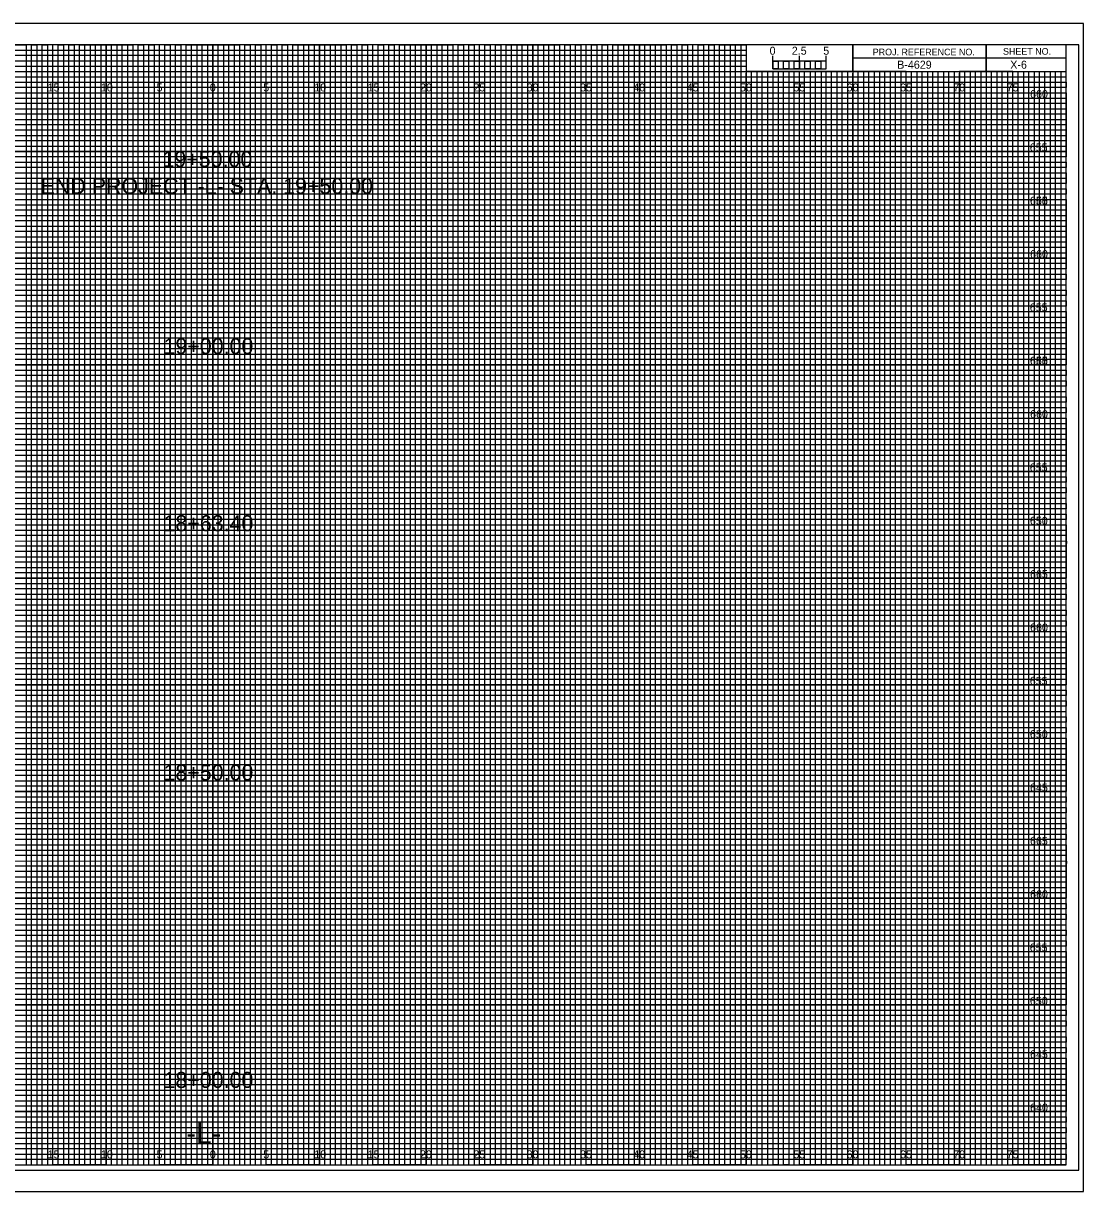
# Model space of a CAD drawing. Extents: x -7 to 162, y 548 to 657.
# Drawn here: x 62.2 to 161.7, y 547.5 to 657 of the extents above; entities that cross this region are included whole.
import ezdxf

# ---------------------------------------------------------------- set-up
doc = ezdxf.new("R2010")
doc.units = 0
for name, color, linetype in [('Exist CMT Pavement', 7, 'Continuous'), ('Exist Cross Section Cell', 7, 'Continuous'), ('Exist XS Center Line Elevation Label', 7, 'Continuous'), ('Exist XS Ground Line', 7, 'Continuous'), ('Prop CMT Pvmt Course 1 Wedge', 7, 'Continuous'), ('Prop CMT Pvmt Course 2 Wedge', 7, 'Continuous'), ('Prop CMT Pvmt Course 3 Wedge', 7, 'Continuous'), ('Prop CMT Pvmt Surface', 7, 'Continuous'), ('Prop CMT Pvmt Surface Shoulder', 7, 'Continuous'), ('Prop CMT Pvmt Wedge Surface 1', 7, 'Continuous'), ('Prop CMT Pvmt Wedge Surface 2', 7, 'Continuous'), ('Prop CMT Shld Paved Course 1', 7, 'Continuous'), ('Prop CMT Shld Paved Course 2', 7, 'Continuous'), ('Prop CMT Shld Paved Course 3', 7, 'Continuous'), ('Prop CMT Slope Grass', 7, 'Continuous'), ('Prop CMT Subgrade Earthwork', 7, 'Continuous'), ('Prop XS EOT Tick Mark', 7, 'Continuous')]:
    doc.layers.add(name, color=color, linetype=linetype)

msp = doc.modelspace()

# ---------------------------------------------------------------- linework, layer by layer
at = {"layer": 'Exist XS Center Line Elevation Label'}
for points in [[(57.5, 655), (62.5, 655), (62.5, 550), (67.5, 550), (67.5, 655), (72.5, 655), (72.5, 550), (77.5, 550), (77.5, 655), (82.5, 655), (82.5, 550), (87.5, 550), (87.5, 655), (92.5, 655), (92.5, 550), (97.5, 550), (97.5, 655), (102.5, 655), (102.5, 550), (107.5, 550), (107.5, 655), (112.5, 655), (112.5, 550), (117.5, 550), (117.5, 655), (122.5, 655), (122.5, 550), (127.5, 550), (127.5, 655), (129.97, 655), (130, 655), (130, 652.5), (132.5, 652.5), (132.5, 550), (137.5, 550), (137.5, 652.5), (142.5, 652.5), (142.5, 550), (147.5, 550), (147.5, 652.5), (152.5, 652.5), (152.5, 550), (157.5, 550), (157.5, 652.5)], [(0, 652.5), (137.5, 652.5)], [(0, 642.5), (160, 642.5), (160, 647.5), (0, 647.5)], [(0, 632.5), (160, 632.5), (160, 637.5), (0, 637.5)], [(0, 622.5), (160, 622.5), (160, 627.5), (0, 627.5)], [(0, 612.5), (160, 612.5), (160, 617.5), (0, 617.5)], [(0, 602.5), (160, 602.5), (160, 607.5), (0, 607.5)], [(0, 592.5), (160, 592.5), (160, 597.5), (0, 597.5)], [(0, 582.5), (160, 582.5), (160, 587.5), (0, 587.5)], [(0, 572.5), (160, 572.5), (160, 577.5), (0, 577.5)], [(0, 562.5), (160, 562.5), (160, 567.5), (0, 567.5)], [(0, 552.5), (160, 552.5), (160, 557.5), (0, 557.5)]]:
    msp.add_lwpolyline(points, dxfattribs=at)
at = {"layer": 'Exist XS Ground Line'}
for p, q in [((65, 655), (60, 655)), ((65, 550), (65, 655)), ((75, 655), (70, 655)), ((70, 655), (70, 550)), ((75, 550), (75, 655)), ((85, 655), (80, 655)), ((80, 655), (80, 550)), ((85, 550), (85, 655)), ((95, 655), (90, 655)), ((90, 655), (90, 550)), ((95, 550), (95, 655)), ((105, 655), (100, 655)), ((100, 655), (100, 550)), ((105, 550), (105, 655)), ((115, 655), (110, 655)), ((110, 655), (110, 550)), ((115, 550), (115, 655)), ((125, 655), (120, 655)), ((120, 655), (120, 550)), ((125, 550), (125, 655)), ((130, 655), (130, 550)), ((135, 550), (135, 652.5)), ((145, 652.5), (140, 652.5)), ((140, 652.5), (140, 550)), ((145, 550), (145, 652.5)), ((155, 652.5), (150, 652.5)), ((150, 652.5), (150, 550)), ((155, 550), (155, 652.5)), ((70, 550), (65, 550)), ((80, 550), (75, 550)), ((90, 550), (85, 550)), ((100, 550), (95, 550)), ((110, 550), (105, 550)), ((120, 550), (115, 550)), ((130, 550), (125, 550)), ((140, 550), (135, 550)), ((150, 550), (145, 550)), ((160, 550), (155, 550)), ((160, 550), (160, 550))]:
    msp.add_line(p, q, dxfattribs=at)
for points in [[(0, 650), (160, 650), (160, 645), (0, 645)], [(0, 640), (160, 640), (160, 635), (0, 635)], [(0, 630), (160, 630), (160, 625), (0, 625)], [(0, 620), (160, 620), (160, 615), (0, 615)], [(0, 610), (160, 610), (160, 605), (0, 605)], [(0, 600), (160, 600), (160, 595), (0, 595)], [(0, 590), (160, 590), (160, 585), (0, 585)], [(0, 580), (160, 580), (160, 575), (0, 575)], [(0, 570), (160, 570), (160, 565), (0, 565)], [(0, 560), (160, 560), (160, 555), (0, 555)]]:
    msp.add_lwpolyline(points, dxfattribs=at)
at = {"layer": 'Prop CMT Pvmt Course 1 Wedge'}
for p, q in [((161.65, 657), (-6.7, 657)), ((-6.7, 547.5), (161.65, 547.5))]:
    msp.add_line(p, q, dxfattribs=at)
at = {"layer": 'Prop CMT Pvmt Surface'}
for p, q in [((133.5, 652.5), (133, 652.5)), ((133, 652.5), (133, 550)), ((133.5, 550), (133.5, 652.5)), ((134.5, 652.5), (134, 652.5)), ((134, 652.5), (134, 550)), ((134.5, 550), (134.5, 652.5)), ((133, 550), (132.5, 550)), ((134, 550), (133.5, 550))]:
    msp.add_line(p, q, dxfattribs=at)
for points in [[(62.5, 550), (63, 550), (63, 655), (63.5, 655), (63.5, 550)], [(63.5, 550), (64, 550), (64, 655), (64.5, 655), (64.5, 550)], [(65, 550), (65.5, 550), (65.5, 655), (66, 655), (66, 550)], [(66, 550), (66.5, 550), (66.5, 655), (67, 655), (67, 550)], [(67.5, 550), (68, 550), (68, 655), (68.5, 655), (68.5, 550)], [(68.5, 550), (69, 550), (69, 655), (69.5, 655), (69.5, 550)], [(70, 550), (70.5, 550), (70.5, 655), (71, 655), (71, 550)], [(71, 550), (71.5, 550), (71.5, 655), (72, 655), (72, 550)], [(72.5, 550), (73, 550), (73, 655), (73.5, 655), (73.5, 550)], [(73.5, 550), (74, 550), (74, 655), (74.5, 655), (74.5, 550)], [(75, 550), (75.5, 550), (75.5, 655), (76, 655), (76, 550)], [(76, 550), (76.5, 550), (76.5, 655), (77, 655), (77, 550)], [(77.5, 550), (78, 550), (78, 655), (78.5, 655), (78.5, 550)], [(78.5, 550), (79, 550), (79, 655), (79.5, 655), (79.5, 550)], [(80, 550), (80.5, 550), (80.5, 655), (81, 655), (81, 550)], [(81, 550), (81.5, 550), (81.5, 655), (82, 655), (82, 550)], [(82.5, 550), (83, 550), (83, 655), (83.5, 655), (83.5, 550)], [(83.5, 550), (84, 550), (84, 655), (84.5, 655), (84.5, 550)], [(85, 550), (85.5, 550), (85.5, 655), (86, 655), (86, 550)], [(86, 550), (86.5, 550), (86.5, 655), (87, 655), (87, 550)], [(87.5, 550), (88, 550), (88, 655), (88.5, 655), (88.5, 550)], [(88.5, 550), (89, 550), (89, 655), (89.5, 655), (89.5, 550)], [(90, 550), (90.5, 550), (90.5, 655), (91, 655), (91, 550)], [(91, 550), (91.5, 550), (91.5, 655), (92, 655), (92, 550)], [(92.5, 550), (93, 550), (93, 655), (93.5, 655), (93.5, 550)], [(93.5, 550), (94, 550), (94, 655), (94.5, 655), (94.5, 550)], [(95, 550), (95.5, 550), (95.5, 655), (96, 655), (96, 550)], [(96, 550), (96.5, 550), (96.5, 655), (97, 655), (97, 550)], [(97.5, 550), (98, 550), (98, 655), (98.5, 655), (98.5, 550)], [(98.5, 550), (99, 550), (99, 655), (99.5, 655), (99.5, 550)], [(100, 550), (100.5, 550), (100.5, 655), (101, 655), (101, 550)], [(101, 550), (101.5, 550), (101.5, 655), (102, 655), (102, 550)], [(102.5, 550), (103, 550), (103, 655), (103.5, 655), (103.5, 550)], [(103.5, 550), (104, 550), (104, 655), (104.5, 655), (104.5, 550)], [(105, 550), (105.5, 550), (105.5, 655), (106, 655), (106, 550)], [(106, 550), (106.5, 550), (106.5, 655), (107, 655), (107, 550)], [(107.5, 550), (108, 550), (108, 655), (108.5, 655), (108.5, 550)], [(108.5, 550), (109, 550), (109, 655), (109.5, 655), (109.5, 550)], [(110, 550), (110.5, 550), (110.5, 655), (111, 655), (111, 550)], [(111, 550), (111.5, 550), (111.5, 655), (112, 655), (112, 550)], [(112.5, 550), (113, 550), (113, 655), (113.5, 655), (113.5, 550)], [(113.5, 550), (114, 550), (114, 655), (114.5, 655), (114.5, 550)], [(115, 550), (115.5, 550), (115.5, 655), (116, 655), (116, 550)], [(116, 550), (116.5, 550), (116.5, 655), (117, 655), (117, 550)], [(117.5, 550), (118, 550), (118, 655), (118.5, 655), (118.5, 550)], [(118.5, 550), (119, 550), (119, 655), (119.5, 655), (119.5, 550)], [(120, 550), (120.5, 550), (120.5, 655), (121, 655), (121, 550)], [(121, 550), (121.5, 550), (121.5, 655), (122, 655), (122, 550)], [(122.5, 550), (123, 550), (123, 655), (123.5, 655), (123.5, 550)], [(123.5, 550), (124, 550), (124, 655), (124.5, 655), (124.5, 550)], [(125, 550), (125.5, 550), (125.5, 655), (126, 655), (126, 550)], [(126, 550), (126.5, 550), (126.5, 655), (127, 655), (127, 550)], [(127.5, 550), (128, 550), (128, 655), (128.5, 655), (128.5, 550)], [(128.5, 550), (129, 550), (129, 655), (129.5, 655), (129.5, 550)], [(130, 550), (130.5, 550), (130.5, 652.5), (131.01, 652.5), (131.01, 550)], [(131, 550), (131.5, 550), (131.5, 652.5), (132, 652.5), (132, 550)], [(135, 550), (135.49, 550), (135.49, 652.5), (136, 652.5), (136, 550)], [(136, 550), (136.5, 550), (136.5, 652.5), (137.03, 652.5), (137.03, 550)], [(137.5, 550), (138, 550), (138, 652.5), (138.5, 652.5), (138.5, 550)], [(138.5, 550), (139, 550), (139, 652.5), (139.5, 652.5), (139.5, 550)], [(140, 550), (140.5, 550), (140.5, 652.5), (141, 652.5), (141, 550)], [(141, 550), (141.5, 550), (141.5, 652.5), (142, 652.5), (142, 550)], [(142.5, 550), (143, 550), (143, 652.5), (143.5, 652.5), (143.5, 550)], [(143.5, 550), (144, 550), (144, 652.5), (144.5, 652.5), (144.5, 550)], [(145, 550), (145.5, 550), (145.5, 652.5), (146, 652.5), (146, 550)], [(146, 550), (146.5, 550), (146.5, 652.5), (147, 652.5), (147, 550)], [(147.5, 550), (148, 550), (148, 652.5), (148.5, 652.5), (148.5, 550)], [(148.5, 550), (149, 550), (149, 652.5), (149.5, 652.5), (149.5, 550)], [(150, 550), (150.5, 550), (150.5, 652.5), (151, 652.5), (151, 550)], [(151, 550), (151.5, 550), (151.5, 652.5), (152, 652.5), (152, 550)], [(152.5, 550), (153, 550), (153, 652.5), (153.5, 652.5), (153.5, 550)], [(153.5, 550), (154, 550), (154, 652.5), (154.5, 652.5), (154.5, 550)], [(155, 550), (155.5, 550), (155.5, 652.5), (156, 652.5), (156, 550)], [(156, 550), (156.5, 550), (156.5, 652.5), (157, 652.5), (157, 550)], [(157.5, 550), (158, 550), (158, 652.5), (158.5, 652.5), (158.5, 550)], [(158.5, 550), (159, 550), (159, 652.5), (159.5, 652.5), (159.5, 550)]]:
    msp.add_lwpolyline(points, dxfattribs=at)
at = {"layer": 'Prop CMT Pvmt Surface Shoulder'}
for p, q in [((132.5, 652.75), (132.5, 653.95)), ((132.5, 653.45), (132.5, 653.95)), ((135, 652.75), (135, 653.95)), ((137.5, 652.75), (137.5, 653.95)), ((137.5, 653.45), (137.5, 653.95))]:
    msp.add_line(p, q, dxfattribs=at)
for points in [[(137.5, 653.45), (132.5, 653.45), (132.5, 652.75), (137.5, 652.75)], [(132.5, 653.45), (133, 653.45), (133, 652.75), (132.5, 652.75)], [(133.5, 653.45), (134, 653.45), (134, 652.75), (133.5, 652.75)], [(134.5, 653.45), (135, 653.45), (135, 652.75), (134.5, 652.75)], [(135.5, 653.45), (136, 653.45), (136, 652.75), (135.5, 652.75)], [(136.5, 653.45), (137, 653.45), (137, 652.75), (136.5, 652.75)]]:
    msp.add_lwpolyline(points, close=True, dxfattribs=at)
at = {"layer": 'Prop CMT Shld Paved Course 1'}
msp.add_lwpolyline([(-6.7, 547.5), (161.65, 547.5), (161.65, 657), (-6.7, 657)], close=True, dxfattribs=at)
at = {"layer": 'Prop CMT Shld Paved Course 2'}
msp.add_lwpolyline([(-5.4, 549.5), (161.2, 549.5), (161.2, 655), (-5.4, 655)], close=True, dxfattribs=at)
at = {"layer": 'Prop CMT Shld Paved Course 3'}
for p, q in [((65, 550), (65, 655)), ((70, 550), (70, 655)), ((75, 550), (75, 655)), ((80, 550), (80, 655)), ((85, 550), (85, 655)), ((90, 550), (90, 655)), ((95, 550), (95, 655)), ((100, 550), (100, 655)), ((105, 550), (105, 655)), ((110, 550), (110, 655)), ((115, 550), (115, 655)), ((120, 550), (120, 655)), ((125, 550), (125, 655)), ((130, 550), (130, 652.34)), ((135, 550), (135, 652.34)), ((140, 550), (140, 652.34)), ((145, 550), (145, 652.34)), ((150, 550), (150, 652.34)), ((155, 550), (155, 652.34)), ((0, 650), (160, 650)), ((0, 645), (160, 645)), ((0, 640), (160, 640)), ((0, 635), (160, 635)), ((0, 630), (160, 630)), ((0, 625), (160, 625)), ((0, 620), (160, 620)), ((0, 615), (160, 615)), ((0, 610), (160, 610)), ((0, 605), (160, 605)), ((0, 600), (160, 600)), ((0, 595), (160, 595)), ((0, 590), (160, 590)), ((0, 585), (160, 585)), ((0, 580), (160, 580)), ((0, 575), (160, 575)), ((0, 570), (160, 570)), ((0, 565), (160, 565)), ((0, 560), (160, 560)), ((0, 555), (160, 555))]:
    msp.add_line(p, q, dxfattribs=at)
at = {"layer": 'Prop CMT Slope Grass'}
for p, q in [((152.5, 655), (152.5, 652.5)), ((152.5, 652.5), (152.5, 655)), ((160, 653.75), (140, 653.75)), ((140, 653.75), (140, 652.5)), ((140, 652.5), (160, 652.5))]:
    msp.add_line(p, q, dxfattribs=at)
for points in [[(160, 655), (0, 655), (0, 550), (160, 550)], [(140, 655), (130, 655), (130, 652.51), (140, 652.51)], [(160, 655), (140, 655), (140, 652.5), (160, 652.5)]]:
    msp.add_lwpolyline(points, close=True, dxfattribs=at)
at = {"layer": 'Prop XS EOT Tick Mark'}
for p, q in [((0, 654.5), (130, 654.5)), ((130, 653.99), (0, 653.99)), ((130, 654.5), (130, 653.99)), ((0, 653.5), (130, 653.5)), ((130, 652.95), (0, 652.95)), ((130, 653.5), (130, 652.95)), ((0, 652), (160, 652))]:
    msp.add_line(p, q, dxfattribs=at)
for points in [[(0, 651.5), (135, 651.5), (160, 651.5), (160, 651), (0, 651)], [(0, 650.5), (160, 650.5), (160, 649.5), (0, 649.5)], [(0, 649), (160, 649), (160, 648.5), (0, 648.49)], [(0, 648), (160, 648), (160, 647), (0, 647)], [(0, 646.5), (160, 646.5), (160, 646), (0, 646)], [(0, 645.5), (160, 645.5), (160, 644.5), (0, 644.5)], [(0, 644), (160, 644), (160, 643.5), (0, 643.5)], [(0, 643), (160, 643), (160, 642), (0, 642)], [(0, 641.5), (160, 641.5), (160, 641), (0, 641)], [(0, 640.5), (160, 640.5), (160, 639.5), (0, 639.5)], [(0, 639), (160, 639), (160, 638.5), (0, 638.5)], [(0, 638), (160, 638), (160, 636.98), (160, 636.5), (160, 636), (0, 636)], [(0, 637), (160, 637), (160, 636.5), (0, 636.5)], [(0, 635.5), (160, 635.5), (160, 634.5), (0, 634.51)], [(0, 634.51), (160, 634.5), (160, 634), (0, 634)], [(0, 633.5), (160, 633.5), (160, 633), (0, 633)], [(0, 632), (160, 632), (160, 631.5), (0, 631.5)], [(0, 631), (160, 631), (160, 630.5), (0, 630.5)], [(-0.04, 629.45), (160, 629.45), (160, 628.94), (-0.04, 628.94)], [(0, 628.5), (160, 628.5), (160, 628), (0, 628)], [(0, 627), (160, 627), (160, 626.5), (0, 626.5)], [(0, 626), (160, 626), (160, 625.5), (0, 625.5)], [(0, 624.5), (160, 624.5), (160, 624), (0, 624)], [(0, 623.5), (160, 623.5), (160, 623), (0, 623)], [(0, 622), (160, 622), (160, 621.5), (0, 621.5)], [(0, 621), (160, 621), (160, 620.5), (0, 620.5)], [(0, 619.5), (160, 619.5), (160, 618.99), (0, 619)], [(0, 618.5), (160, 618.5), (160, 618), (0, 618)], [(0, 617), (160, 617), (160, 616.5), (0, 616.5)], [(0, 616), (160, 616), (160, 615.5), (0, 615.5)], [(0, 614.5), (160, 614.5), (160, 614), (0, 614)], [(0, 613.5), (160, 613.5), (160, 613), (0, 613)], [(0, 612), (160, 612), (160, 611.5), (0, 611.5)], [(0, 611), (160, 611), (160, 610.5), (0, 610.5)], [(0, 609.5), (160, 609.5), (160, 609), (0, 609)], [(0, 608.5), (160.03, 608.46), (160, 608), (0, 608)], [(0, 607), (160, 607), (160, 606.5), (0, 606.5)], [(0, 606), (160, 606), (160, 605.5), (0, 605.5)], [(0, 604.5), (160, 604.5), (160, 604), (0, 604)], [(0, 603.5), (160, 603.5), (160, 603), (0, 603)], [(0, 602), (160, 602), (160, 601.5), (0, 601.5)], [(0, 601), (160, 601), (160, 600.5), (0, 600.5)], [(0, 599.5), (160, 599.5), (160, 599), (0, 599)], [(0, 598.5), (160, 598.5), (160, 598), (0, 598)], [(0, 597), (160, 597), (160, 596.5), (0, 596.5)], [(0, 596), (160, 596), (160, 595.5), (0, 595.5)], [(0, 594.5), (160, 594.5), (160, 594), (0, 594)], [(0, 593.5), (160, 593.5), (160, 593), (0, 593)], [(0, 592), (160, 592), (160, 591.5), (0, 591.5)], [(0, 591), (160, 591), (160, 590.5), (0, 590.5)], [(0, 589.5), (160, 589.5), (160, 588.99), (0, 589)], [(0, 588.5), (160, 588.5), (160, 588), (0, 588)], [(0, 587), (160, 587), (160, 586.5), (0, 586.5)], [(0, 586), (160, 586), (160, 585.5), (0, 585.5)], [(0, 584.5), (160, 584.5), (160, 584), (0, 584)], [(0, 583.5), (160, 583.5), (160, 583), (0, 583)], [(0, 582), (160, 582), (160, 581.5), (0, 581.5)], [(0, 581), (160, 581), (160, 580.5), (0, 580.5)], [(0, 579.5), (160, 579.5), (160, 579), (0, 579)], [(0, 578.5), (160.03, 578.46), (160, 578), (0, 578)], [(0, 577), (160, 577), (160, 576.5), (0, 576.5)], [(0, 576), (160, 576), (160, 575.5), (0, 575.5)], [(0, 574.5), (160, 574.5), (160, 574), (0, 574)], [(0, 573.5), (160, 573.5), (160, 573), (0, 573)], [(0, 572), (160, 572), (160, 571.5), (0, 571.5)], [(0, 571), (160, 571), (160, 570.5), (0, 570.5)], [(0, 569.5), (160, 569.5), (160, 569), (0, 569)], [(0, 568.5), (160, 568.5), (160, 568), (0, 568)], [(0, 567), (160, 567), (160, 566.5), (0, 566.5)], [(0, 566), (160, 566), (160, 565.5), (0, 565.5)], [(0, 564.5), (160, 564.5), (160, 564), (0, 564)], [(0, 563.5), (160, 563.5), (160, 563), (0, 563)], [(0, 562), (160, 562), (160, 561.5), (0, 561.5)], [(0, 561), (160, 561), (160, 560.5), (0, 560.5)], [(0, 559.5), (160, 559.5), (160, 559), (0, 559)], [(0, 558.5), (160, 558.5), (160, 558), (0, 558)], [(0, 557), (160, 557), (160, 556.5), (0, 556.5)], [(0, 556), (160, 556), (160, 555.5), (0, 555.5)], [(0, 554.5), (160, 554.5), (160, 554), (0, 554)], [(0, 553.5), (160, 553.5), (160, 553), (0, 553)], [(0, 552), (160, 552), (160, 551.5), (0, 551.5)], [(0, 551), (160, 551), (160, 550.5), (0, 550.5)]]:
    msp.add_lwpolyline(points, dxfattribs=at)

# ---------------------------------------------------------------- texts
at = {"layer": 'Exist CMT Pavement'}
msp.add_text('B-4629', height=0.75, dxfattribs=at).set_placement((144.17, 652.75))
at = {"layer": 'Exist Cross Section Cell'}
for s, p in [('15', (64.53, 650.62)), ('10', (69.52, 650.62)), ('5', (74.74, 650.62)), ('0', (79.73, 650.62)), ('0', (79.73, 650.62)), ('5', (84.74, 650.62)), ('10', (89.52, 650.62)), ('15', (94.53, 650.62)), ('20', (99.43, 650.62)), ('25', (104.44, 650.62)), ('30', (109.43, 650.62)), ('35', (114.44, 650.62)), ('40', (119.43, 650.62)), ('45', (124.44, 650.62)), ('50', (129.43, 650.62)), ('55', (134.44, 650.62)), ('60', (139.43, 650.62)), ('65', (144.44, 650.62)), ('70', (149.43, 650.62)), ('75', (154.44, 650.62)), ('15', (64.53, 550.62)), ('10', (69.52, 550.62)), ('5', (74.74, 550.62)), ('0', (79.73, 550.62)), ('0', (79.73, 550.62)), ('5', (84.74, 550.62)), ('10', (89.52, 550.62)), ('15', (94.53, 550.62)), ('20', (99.43, 550.62)), ('25', (104.44, 550.62)), ('30', (109.43, 550.62)), ('35', (114.44, 550.62)), ('40', (119.43, 550.62)), ('45', (124.44, 550.62)), ('50', (129.43, 550.62)), ('55', (134.44, 550.62)), ('60', (139.43, 550.62)), ('65', (144.44, 550.62)), ('70', (149.43, 550.62)), ('75', (154.44, 550.62))]:
    msp.add_text(s, height=0.75, dxfattribs=at).set_placement(p)
at = {"layer": 'Prop CMT Pvmt Course 2 Wedge'}
for s, p in [('660', (156.63, 650)), ('655', (156.6, 645)), ('650', (156.61, 640)), ('665', (156.62, 640)), ('660', (156.63, 635)), ('655', (156.6, 630)), ('650', (156.61, 625)), ('665', (156.62, 625)), ('660', (156.63, 620)), ('655', (156.6, 615)), ('650', (156.61, 610)), ('665', (156.62, 605)), ('660', (156.63, 600)), ('655', (156.6, 595)), ('650', (156.61, 590)), ('645', (156.62, 585)), ('665', (156.62, 580)), ('660', (156.63, 575)), ('655', (156.6, 570)), ('650', (156.61, 565)), ('645', (156.62, 560)), ('640', (156.63, 555))]:
    msp.add_text(s, height=0.75, dxfattribs=at).set_placement(p)
at = {"layer": 'Prop CMT Pvmt Course 3 Wedge'}
for s, p in [('19+50.00', (75.29, 643.53)), ('END PROJECT -L- STA. 19+50.00', (63.87, 641.01)), ('19+00.00', (75.39, 626)), ('18+63.40', (75.39, 609.4)), ('18+50.00', (75.39, 586.04)), ('18+00.00', (75.39, 557.22))]:
    msp.add_text(s, height=1.5, dxfattribs=at).set_placement(p)
at = {"layer": 'Prop CMT Pvmt Surface Shoulder'}
msp.add_text('0', height=0.75, dxfattribs=at).set_placement((132.21, 654.06))
at = {"layer": 'Prop CMT Pvmt Wedge Surface 1'}
msp.add_text('-L-', height=2, dxfattribs=at).set_placement((77.53, 552))
at = {"layer": 'Prop CMT Pvmt Wedge Surface 2'}
for s, p in [('2.5', (134.29, 654.06)), ('5', (137.24, 654.06))]:
    msp.add_text(s, height=0.75, dxfattribs=at).set_placement(p)
at = {"layer": 'Prop CMT Slope Grass'}
for s, p in [('PROJ. REFERENCE NO.', (141.88, 654)), ('SHEET NO.', (154.09, 654.06))]:
    msp.add_text(s, height=0.625, dxfattribs=at).set_placement(p)
at = {"layer": 'Prop CMT Subgrade Earthwork'}
msp.add_text('X-6', height=0.75, dxfattribs=at).set_placement((154.77, 652.75))

doc.saveas('drawing.dxf')
